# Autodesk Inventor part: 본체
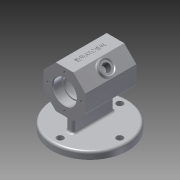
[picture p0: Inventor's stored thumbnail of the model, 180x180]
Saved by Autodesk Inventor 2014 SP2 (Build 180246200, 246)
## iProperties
Created: 2021-02
Part Number: 본체
Material: 알루미늄 6061
Document SubType Name: Modeling
Designer: 거성
Density: 2.71 g/cm^3
Appearance: 알루미늄 - 평지
Mass: 558.812 g
Surface Area: 509.677 cm^2
Volume: 206.204 cm^3
Author: 거성
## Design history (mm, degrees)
sketch "스케치1"
  geometry: C1 r 52 at (0, 0); 1 further point
  constraints: 1 centre point, 1 coincident
  dimensions: "d0" = 104 diameter of C1
extrude "돌출1" new body sketch "스케치1" distance "d1" = 10; taper "d2" = 0 deg
sketch "스케치3"
  geometry: L1 (52, 10)-(-52, 10) reference; L2 (-52, 0)-(52, 0) reference; L3 (12.012, 33)-(-12.012, 33); L4 (-12.012, 33)-(-29, 49.988); L5 (-29, 49.988)-(-29, 74.012); L6 (-29, 74.012)-(-12.012, 91); L7 (-12.012, 91)-(12.012, 91); L8 (12.012, 91)-(29, 74.012); L9 (29, 74.012)-(29, 49.988); L10 (29, 49.988)-(12.012, 33); C1 r 29 at (0, 62); 3 further points
  constraints: 16 end point, 1 centre point, 1 coincident, 1 horizontal, 1 midpoint, 1 tangent, 1 vertical alignment, 17 other
  dimensions: "d12" = 58 diameter of C1; "d13" = 62 distance from line of L2 C1.centre
extrude "돌출2" join sketch "스케치3" stored distance "d14" = 70; taper "d15" = 0 deg
sketch "스케치4"
  geometry: L1 (49.988, 35)-(49.988, -35) reference; L2 (74.012, 35)-(49.988, 35) reference; L3 (74.012, 35)-(74.012, -35) reference; L4 (49.988, -35)-(74.012, -35) reference; L5 (74.012, 35)-(74.012, -35) reference; L6 (91, 35)-(74.012, 35) reference; L7 (91, 35)-(91, -35) reference; L8 (74.012, -35)-(91, -35) reference; L9 (33, 35)-(33, -35) reference; L10 (49.988, 35)-(33, 35) reference; L11 (49.988, 35)-(49.988, -35) reference; L12 (33, -35)-(49.988, -35) reference; L13 (10, -52)-(10, 52) reference; L14 (0, 52)-(0, -52) reference; L15 (62, 35)-(62, -35); L16 (62, 35)-(78, 35); L17 (78, 23)-(76, 23); L18 (76, 23)-(76, 20); L19 (76, 20)-(84, 20); L20 (84, 20)-(84, -20); L21 (84, -20)-(76, -20); L22 (76, -20)-(76, -23); L23 (76, -23)-(78, -23); L24 (78, -23)-(78, -35); L25 (78, 23)-(78, 35); L26 (78, -35)-(62, -35); 1 further point
  constraints: 24 end point, 4 collinear, 4 parallel, 3 perpendicular, 2 midpoint, 2 point on line, 1 horizontal
  dimensions: "d16" = 16 distance between parallel lines of L15 L25; "d17" = 3 distance between parallel lines of L19 L17; "d18" = 12 distance between parallel lines of L17 L16; "d19" = 14 distance between parallel lines of L15 L18; "d20" = 22 distance between parallel lines of L15 L20; "d21" = 40 distance between parallel lines of L21 L19; "d22" = 3 distance between parallel lines of L21 L23
revolve "회전1" sketch "스케치4" stored, may be unused: angle "d23" = 90 deg
sketch "스케치5"
  geometry: C1 r 52 at (0, 0) reference; C2 r 4.5 at (0, 41)
  constraints: 1 centre point, 1 vertical alignment
  dimensions: "d24" = 9 diameter of C2; "d25" = 41 distance of C1.centre C2.centre
extrude "돌출3" cut sketch "스케치5" stored distance "d26" = 70; taper "d27" = 0 deg
fillet "모깎기1" dims "d31" = 3
chamfer "모따기1" distance "d32" = 1; stored, may be unused: second distance "d33" = 2, angle "d34" = 45 deg
fillet "모깎기2" dims "d35" = 0.3
fillet "모깎기3" dims "d36" = 3
sketch "스케치6"
  geometry: C1 r 17 at (0, 62) reference; C2 r 2 at (0, 85); 1 further point
  constraints: 1 centre point, 1 vertical alignment
  dimensions: "d37" = 23 distance of C1.centre C2.centre; "d38" = 4 diameter of C2
hole "구멍1" sketch "스케치6" at (0, 85) diameter "d39" = 3.242; stored, may be unused: countersink angle "d43" = 90 deg, drill point angle "d45" = 118 deg; dims "d40" = 8, "d41" = 4, "d42" = 2, "d44" = 10
sketch "스케치7"
  geometry: L1 (24.024, 0)-(0, 0) reference; L2 (-16.988, 0)-(-16.988, 70) reference; 2 further points
  constraints: 1 other
  dimensions: "d49" = 29 distance from line of L2 point (12.012, 35); "d50" = 35 distance from line of L1 point (12.012, 35)
feature "엠보싱1" sketch "스케치7" dims "d1" = 10, "d2" = 0, "d51" = 0.5, "d52" = 0
sketch "스케치8"
  geometry: L1 (33, 35)-(33, -35) reference; L2 (49.988, 35)-(33, 35) reference; L3 (49.988, 35)-(49.988, -35) reference; L4 (33, -35)-(49.988, -35) reference; L5 (0, 52)-(0, -52) reference; L6 (7, -52)-(7, 52) reference; L7 (10, 49)-(10, -49) reference; L8 (7, -52)-(7, 52) reference; L9 (10, 49)-(10, -49) reference; L10 (33, 28)-(10, 28); L11 (10, 28)-(10, -28); L12 (10, -28)-(33, -28); L13 (33, -28)-(33, 28); 3 further points
  constraints: 8 end point, 2 collinear, 2 midpoint, 2 parallel, 1 horizontal, 1 horizontal alignment, 1 perpendicular
  dimensions: "d53" = 56 distance between parallel lines of L12 L10
extrude "돌출4" join sketch "스케치8" stored distance "d54" = 10; taper "d55" = 0 deg
fillet "모깎기4" dims "d56" = 3
fillet "모깎기5" dims "d57" = 3
sketch "스케치9"
  geometry: L1 (16.988, 70)-(16.988, 0) reference; C1 r 10 at (-12.012, 35); 1 further point
  constraints: 1 centre point, 1 horizontal alignment
  dimensions: "d58" = 20 diameter of C1; "d59" = 29 distance from line of L1 C1.centre
extrude "돌출5" join sketch "스케치9" distance "d60" = 5; taper "d61" = 0 deg
fillet "모깎기6" dims "d62" = 1
hole "구멍2" diameter "d65" = 10.917; stored, may be unused: countersink angle "d69" = 90 deg, drill point angle "d71" = 118 deg; dims "d66" = 21, "d67" = 16, "d68" = 2, "d70" = 21.25, "d72" = 10, "d73" = 10
chamfer "모따기2" distance "d75" = 1; stored, may be unused: second distance "d76" = 2, angle "d77" = 45 deg
fillet "모깎기8" dims "d78" = 1
node "솔리드1"
pattern_circular "원형 패턴1" dims angle "d29" = 360 deg
pattern_circular "원형 패턴2" dims angle "d47" = 360 deg
mirror "대칭1"
node "투영된 루프2"
node "투영된 루프3"
node "투영된 루프4"
node "투영된 루프5"
node "투영된 루프6"
node "투영된 루프7"
node "투영된 루프8"
node "투영된 루프9"
